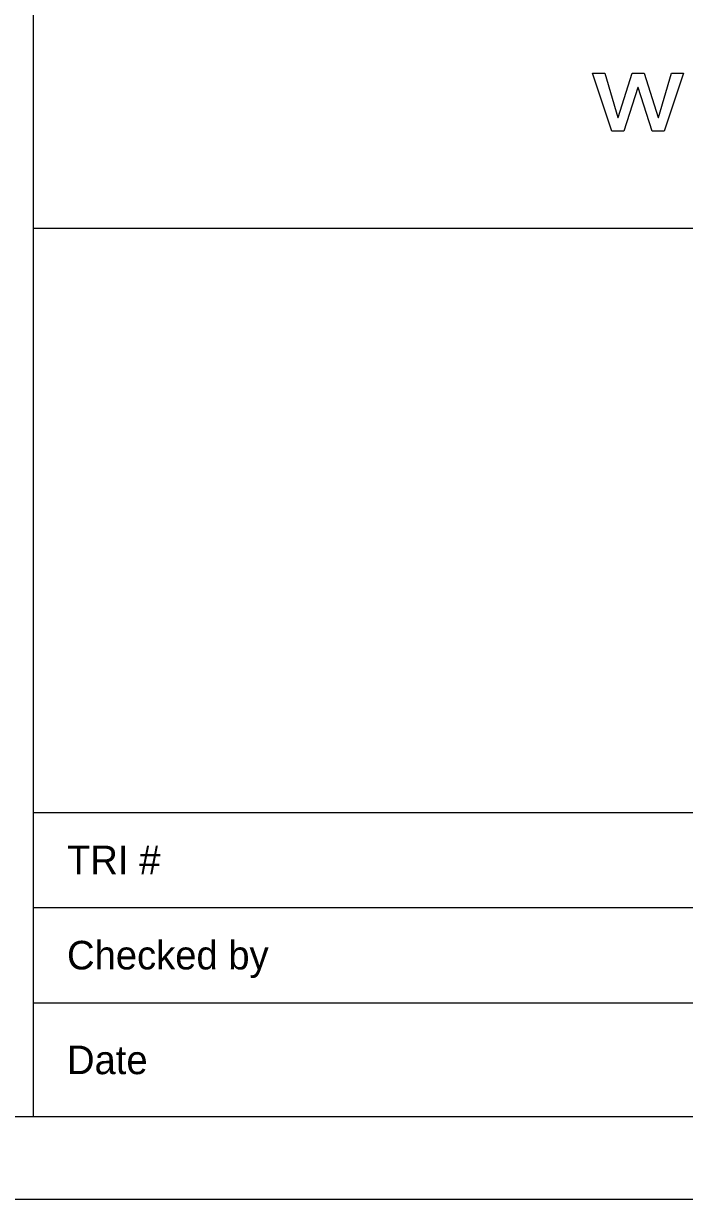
# Model space of a CAD drawing. Extents: x 612883 to 613093, y 4825734 to 4825879.
# Drawn here: x 613058.24 to 613068.66, y 4825733.63 to 4825752.15 of the extents above; entities that cross this region are included whole.
import ezdxf

# ---------------------------------------------------------------- set-up
doc = ezdxf.new("R2010")
doc.units = 0
for name, color, linetype in [('G-ANNO-TTLB-TEXT', 7, 'Continuous'), ('G-TTLB-LOGO', 7, 'Continuous'), ('G-TTLB-OTLN', 7, 'Continuous'), ('G-TTLB-OTLN-PB', 7, 'Continuous')]:
    doc.layers.add(name, color=color, linetype=linetype)

msp = doc.modelspace()

# ---------------------------------------------------------------- linework, layer by layer
at = {"layer": 'G-TTLB-LOGO'}
for p, q in [((613067.514, 4825750.459), (613067.21, 4825751.369)), ((613067.21, 4825751.369), (613067.406, 4825751.369)), ((613067.406, 4825751.369), (613067.612, 4825750.674)), ((613067.616, 4825750.674), (613067.833, 4825751.369)), ((613067.833, 4825751.369), (613068.023, 4825751.369)), ((613068.023, 4825751.369), (613068.244, 4825750.674)), ((613068.248, 4825750.674), (613068.453, 4825751.369)), ((613068.643, 4825751.369), (613068.342, 4825750.459)), ((613068.453, 4825751.369), (613068.643, 4825751.369)), ((613067.925, 4825751.143), (613067.702, 4825750.459)), ((613067.929, 4825751.143), (613067.925, 4825751.143)), ((613068.153, 4825750.459), (613067.929, 4825751.143)), ((613067.612, 4825750.674), (613067.616, 4825750.674)), ((613068.244, 4825750.674), (613068.248, 4825750.674)), ((613067.702, 4825750.459), (613067.514, 4825750.459)), ((613068.342, 4825750.459), (613068.153, 4825750.459))]:
    msp.add_line(p, q, dxfattribs=at)
msp.add_lwpolyline([(613067.406, 4825751.369), (613067.612, 4825750.674), (613067.616, 4825750.674), (613067.833, 4825751.369), (613068.023, 4825751.369), (613068.244, 4825750.674), (613068.248, 4825750.674), (613068.453, 4825751.369), (613068.643, 4825751.369), (613068.342, 4825750.459), (613068.153, 4825750.459), (613067.929, 4825751.143), (613067.925, 4825751.143), (613067.702, 4825750.459), (613067.514, 4825750.459), (613067.21, 4825751.369), (613067.406, 4825751.369)], dxfattribs=at)
at = {"layer": 'G-TTLB-OTLN'}
for p, q in [((613058.399, 4825734.927), (613058.399, 4825869.211)), ((613090.1, 4825748.926), (613058.399, 4825748.926)), ((613058.399, 4825739.726), (613090.1, 4825739.726)), ((613058.399, 4825738.226), (613077.723, 4825738.226)), ((613058.399, 4825736.726), (613077.723, 4825736.726))]:
    msp.add_line(p, q, dxfattribs=at)
msp.add_lwpolyline([(612893.053, 4825869.211), (613090.1, 4825869.211), (613090.1, 4825734.927), (612893.053, 4825734.927)], close=True, dxfattribs=at)
at = {"layer": 'G-TTLB-OTLN-PB'}
msp.add_lwpolyline([(612882.799, 4825870.511), (613093.146, 4825870.511), (613093.146, 4825733.627), (612882.799, 4825733.627)], close=True, dxfattribs=at)

# ---------------------------------------------------------------- texts
at = {"layer": 'G-ANNO-TTLB-TEXT'}
for s, p in [('TRI #', (613058.929, 4825738.751)), ('Checked by', (613058.929, 4825737.251)), ('Date', (613058.929, 4825735.601))]:
    msp.add_text(s, height=0.45, dxfattribs=at).set_placement(p)

doc.saveas('drawing.dxf')
